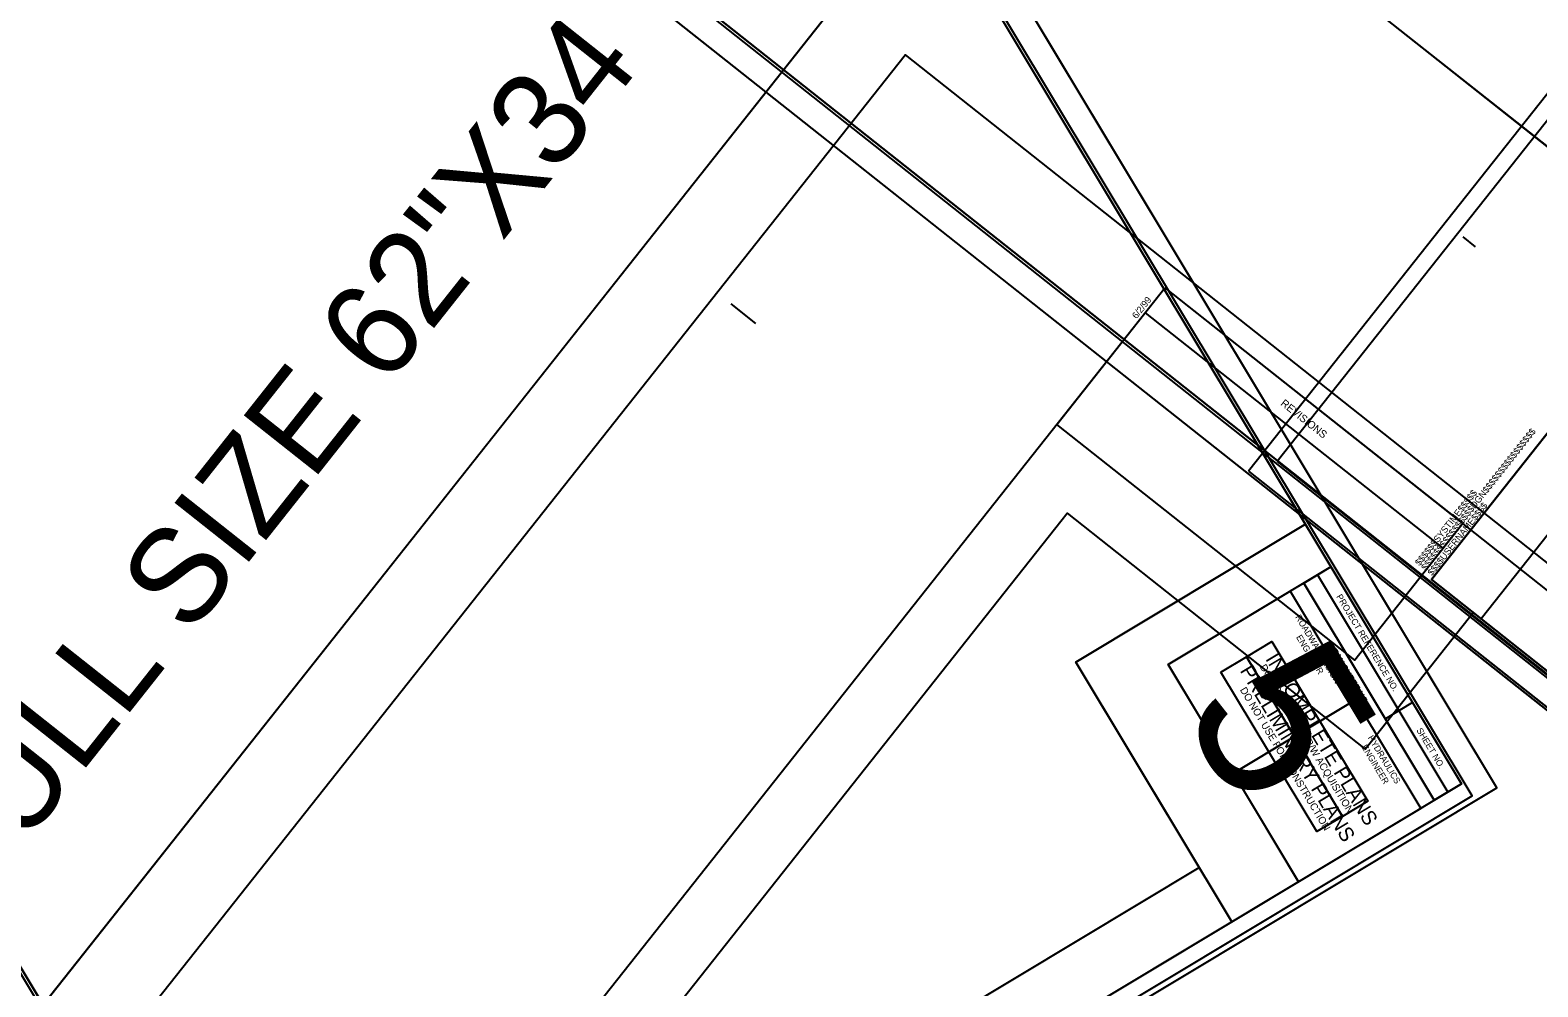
# Model space of a CAD drawing. Extents: x 1778994 to 1784559, y 810461 to 816654.
# Drawn here: x 1780952 to 1782142, y 813872 to 814627 of the extents above; entities that cross this region are included whole.
import ezdxf

# ---------------------------------------------------------------- set-up
doc = ezdxf.new("R2010")
doc.units = 0
for name, color, linetype in [('Sheet Clip Boundary CELL', 7, 'Continuous'), ('Sheet Cutting Line CELL', 7, 'Continuous'), ('Sheet Detail CELL', 7, 'Continuous'), ('Sheet Layout Plan Border', 7, 'Continuous'), ('Sheet North Arrow Point CELL', 7, 'Continuous'), ('Sheet Plan CELL', 7, 'Continuous'), ('Sheet Plan Layout CELL', 7, 'Continuous'), ('Sheet Plot Border Inside CELL', 7, 'Continuous'), ('Sheet Plot Border Outside CELL', 7, 'Continuous'), ('Sheet Sticker Incomplete CELL', 7, 'Continuous'), ('Sheet Sticker Preliminary CELL', 7, 'Continuous')]:
    doc.layers.add(name, color=color, linetype=linetype)

msp = doc.modelspace()

# ---------------------------------------------------------------- linework, layer by layer
at = {"layer": 'Sheet Clip Boundary CELL'}
for points in [[(1781330.1, 814767.8), (1782427.7, 813898.8), (1782948.2, 814556.2), (1782799.8, 814673.7), (1782931.1, 814839.5), (1781981.8, 815591.1)], [(1780435.2, 814734.2), (1781156.3, 813534.2), (1781875, 813966.1), (1781777.6, 814128.3), (1781958.8, 814237.2), (1781335.3, 815275)], [(1782097.5, 814162.5), (1783195.2, 813293.5), (1783715.7, 813950.9), (1783567.3, 814068.4), (1783698.6, 814234.2), (1782749.3, 814985.7)], [(1780971.5, 813236.4), (1781770.7, 814245.9), (1782005.9, 814059.6), (1782091.3, 814167.4), (1783972.9, 812677.7), (1783879.8, 812560.1), (1784036.6, 812435.9), (1783245.2, 811436.3)]]:
    msp.add_lwpolyline(points, close=True, dxfattribs=at)
at = {"layer": 'Sheet Cutting Line CELL'}
for p, q in [((1782110.1, 814029.1), (1781243, 815472.2)), ((1782593.5, 815137.7), (1781913.8, 814279.2)), ((1781087.8, 814930.9), (1782407.7, 813885.9)), ((1781749.7, 814852.4), (1780384.1, 813127.6)), ((1784390.3, 812761.8), (1781749.7, 814852.4)), ((1781913.8, 814279.2), (1783233.7, 813234.2))]:
    msp.add_line(p, q, dxfattribs=at)
at = {"layer": 'Sheet Detail CELL'}
for p, q in [((1781847.9, 814423.9), (1781847.9, 814423.9)), ((1781505, 814411.3), (1781524.6, 814395.7)), ((1781832.4, 814404.3), (1782067.1, 814218.5)), ((1781948.8, 814312.5), (1781948.8, 814312.5)), ((1782002.8, 814301.3), (1782002.8, 814301.3)), ((1782002.8, 814301.3), (1782080.1, 814239.9))]:
    msp.add_line(p, q, dxfattribs=at)
for points in [[(1781847.9, 814423.9), (1784200, 812561.7), (1783175.8, 811268.1), (1780823.7, 813130.3)], [(1781847.9, 814423.9), (1782083.1, 814237.7), (1781997.8, 814129.9), (1781762.6, 814316.1)]]:
    msp.add_lwpolyline(points, close=True, dxfattribs=at)
at = {"layer": 'Sheet Layout Plan Border'}
for points in [[(1781330.1, 814767.8), (1782427.7, 813898.8), (1782948.2, 814556.2), (1782799.8, 814673.7), (1782931.1, 814839.5), (1781981.8, 815591.1)], [(1780435.2, 814734.2), (1781156.3, 813534.2), (1781875, 813966.1), (1781777.6, 814128.3), (1781958.8, 814237.2), (1781335.3, 815275)], [(1782097.5, 814162.5), (1783195.2, 813293.5), (1783715.7, 813950.9), (1783567.3, 814068.4), (1783698.6, 814234.2), (1782749.3, 814985.7)]]:
    msp.add_lwpolyline(points, close=True, dxfattribs=at)
at = {"layer": 'Sheet North Arrow Point CELL'}
msp.add_line((1781881.5, 814224.4), (1781881.5, 814224.4), dxfattribs=at)
at = {"layer": 'Sheet Plan CELL'}
for p, q in [((1782083.1, 814464.1), (1782092.9, 814456.3)), ((1781957.5, 814190.7), (1781946.8, 814184.3)), ((1781957.5, 814190.7), (1782060.6, 814019.2)), ((1781957.5, 814190.7), (1782060.6, 814019.2)), ((1781968.3, 814197.2), (1782071.3, 814025.7)), ((1782058.3, 814193.5), (1782058.3, 814193.5)), ((1781998.4, 814098.5), (1781902, 814040.6)), ((1782043.4, 814096.4), (1782022, 814083.5))]:
    msp.add_line(p, q, dxfattribs=at)
for points in [[(1783060.1, 814737.4), (1781884.1, 815668.5), (1781232.3, 814845.2), (1782408.4, 813914.1)], [(1781232.3, 814845.2), (1781884, 815668.5), (1782903.3, 814861.6), (1782810.1, 814743.9), (1782967, 814619.7), (1782408.4, 813914.1)], [(1782082.1, 814032.1), (1781309.5, 815317.9), (1780409.5, 814777.1), (1781182, 813491.3)], [(1780409.5, 814777.1), (1781309.5, 815317.9), (1781979, 814203.6), (1781850.4, 814126.3), (1781953.4, 813954.8), (1781182, 813491.3)], [(1783886.2, 814085.7), (1782710.1, 815016.8), (1782058.3, 814193.5), (1783234.4, 813262.4)], [(1782058.3, 814193.5), (1782710.1, 815016.8), (1783729.3, 814209.9), (1783636.2, 814092.2), (1783793, 813968), (1783234.4, 813262.4)], [(1781979, 814203.6), (1782082.1, 814032.1), (1782060.6, 814019.2), (1781957.5, 814190.7)], [(1781946.8, 814184.3), (1781998.4, 814098.5), (1781901.9, 814040.6), (1781850.4, 814126.3)], [(1781998.4, 814098.5), (1782049.9, 814012.8), (1781953.4, 813954.8), (1781901.9, 814040.6)]]:
    msp.add_lwpolyline(points, close=True, dxfattribs=at)
at = {"layer": 'Sheet Plan Layout CELL'}
for points in [[(1781884, 815668.5), (1781232.3, 814845.2), (1782408.3, 813914.1), (1782928.8, 814571.6), (1782741.3, 814720.1), (1782872.5, 814885.9)], [(1781309.5, 815317.9), (1780409.5, 814777.1), (1781182, 813491.4), (1781900.8, 813923.2), (1781777.6, 814128.3), (1781958.8, 814237.2)], [(1782710.1, 815016.8), (1782058.3, 814193.5), (1783234.4, 813262.4), (1783754.9, 813919.9), (1783567.3, 814068.4), (1783698.6, 814234.2)], [(1781777.6, 814128.3), (1781900.8, 813923.2), (1782082.1, 814032.1), (1781958.8, 814237.2)]]:
    msp.add_lwpolyline(points, close=True, dxfattribs=at)
at = {"layer": 'Sheet Plot Border Inside CELL'}
for points in [[(1781110.4, 814938.5), (1782416.6, 813904.4), (1783071.5, 814731.6), (1781765.3, 815765.7)], [(1780328.3, 814907.4), (1781186.3, 813479.3), (1782090.6, 814022.7), (1781232.6, 815450.7)], [(1781936.4, 814286.8), (1783242.6, 813252.7), (1783897.5, 814079.9), (1782591.3, 815114)], [(1784230.1, 812559.5), (1781642.9, 814607.9), (1780597.6, 813287.6), (1783184.8, 811239.2)]]:
    msp.add_lwpolyline(points, close=True, dxfattribs=at)
at = {"layer": 'Sheet Plot Border Outside CELL'}
for points in [[(1781087.8, 814930.9), (1782407.7, 813885.9), (1783087.4, 814744.4), (1781767.5, 815789.4)], [(1780304.4, 814908.2), (1781171.5, 813465.2), (1782110.1, 814029.1), (1781243, 815472.2)], [(1781913.8, 814279.2), (1783233.7, 813234.2), (1783913.4, 814092.8), (1782593.5, 815137.7)], [(1784390.3, 812761.8), (1781749.7, 814852.4), (1780384.1, 813127.6), (1783024.7, 811037)]]:
    msp.add_lwpolyline(points, close=True, dxfattribs=at)
at = {"layer": 'Sheet Sticker Incomplete CELL'}
msp.add_lwpolyline([(1781912.3, 814132.5), (1781932.4, 814144.6), (1782008.1, 814018.6), (1781988, 814006.5)], close=True, dxfattribs=at)
at = {"layer": 'Sheet Sticker Preliminary CELL'}
msp.add_lwpolyline([(1781892.1, 814120.4), (1781912.3, 814132.5), (1781988, 814006.5), (1781967.9, 813994.4)], close=True, dxfattribs=at)

# ---------------------------------------------------------------- texts
at = {"layer": 'Sheet Detail CELL'}
for s, height, rotation, p in [('TO PLOT FULL SIZE 62"X34"', 75, 51.6309, (1780624.2, 813575.5)), ('6/2/99', 5.25, 51.6309, (1781825.5, 814399)), ('REVISIONS', 6, 321.6309, (1781938.7, 814331.7))]:
    msp.add_text(s, height=height, rotation=rotation, dxfattribs=at).set_placement(p)
at = {"layer": 'Sheet Plan CELL'}
for s, height, rotation, p in [('$$$$$$$$$$$$$$$$DGN$$$$$$$$$$$$$$$$', 5.25, 51.6309, (1782053.8, 814200.1)), ('$$$$$$SYSTIME$$$$$', 5.25, 51.6309, (1782049, 814203.9)), ('$$$$USERNAME$$$$', 5.25, 51.6309, (1782058.9, 814196.1)), ('PROJECT REFERENCE NO.', 5, 301, (1781983, 814180.1)), ('ROADWAY DESIGN', 5, 301, (1781950.6, 814163.9)), ('ENGINEER', 5, 301, (1781951.3, 814148)), ('R/W SHEET NO.', 5, 301, (1781979, 814137.1)), ('HYDRAULICS', 5, 301, (1782007.8, 814068.6)), ('SHEET NO.', 5, 301, (1782046.3, 814074.5)), ('ENGINEER', 5, 301, (1782002.9, 814061.3))]:
    msp.add_text(s, height=height, rotation=rotation, dxfattribs=at).set_placement(p)
at = {"layer": 'Sheet Plan Layout CELL'}
msp.add_text('5', height=131.3, rotation=301, dxfattribs=at).set_placement((1781859, 814090.6))
at = {"layer": 'Sheet Sticker Incomplete CELL'}
for s, height, p in [('DO NOT USE FOR R/W ACQUISITION', 5.76, (1781922.6, 814124.5)), ('INCOMPLETE PLANS', 11.52, (1781926.9, 814130.9))]:
    msp.add_text(s, height=height, rotation=301, dxfattribs=at).set_placement(p)
at = {"layer": 'Sheet Sticker Preliminary CELL'}
for s, height, p in [('PRELIMINARY PLANS', 11.52, (1781906.8, 814121.6)), ('DO NOT USE FOR CONSTRUCTION', 5.76, (1781906.9, 814106.4))]:
    msp.add_text(s, height=height, rotation=301, dxfattribs=at).set_placement(p)

doc.saveas('drawing.dxf')
